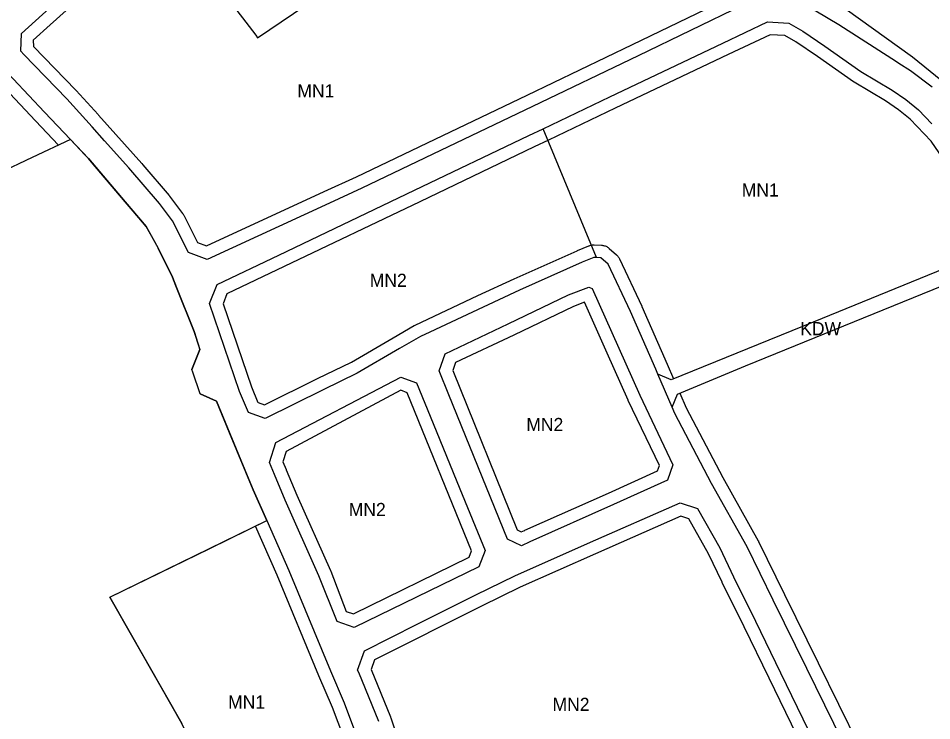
# Model space of a CAD drawing. Extents: x 7435758 to 7439981, y 5550649 to 5554049.
# Drawn here: x 7436744.6 to 7437107.4, y 5551729.4 to 5552008.2 of the extents above; entities that cross this region are included whole.
import ezdxf

# ---------------------------------------------------------------- set-up
doc = ezdxf.new("R2010")
doc.units = 0
for name, color, linetype in [('info', 7, 'Continuous'), ('linie_rozgraniczające', 7, 'Continuous'), ('linie_zabudowy_nieprzekraczalne', 7, 'Continuous'), ('oznaczenia_przeznaczen', 7, 'Continuous')]:
    doc.layers.add(name, color=color, linetype=linetype)

msp = doc.modelspace()

# ---------------------------------------------------------------- linework, layer by layer
at = {"layer": 'info'}
for p, q in [((7436765.31, 5551960.09), (7436750.08, 5551952.93)), ((7436770.99, 5551954.08), (7436765.31, 5551960.09)), ((7436750.08, 5551952.93), (7436736.66, 5551946.62)), ((7436772.47, 5551952.51), (7436770.99, 5551954.08)), ((7436773.71, 5551951.06), (7436772.47, 5551952.51)), ((7436787.1, 5551935.35), (7436773.71, 5551951.06)), ((7436790.22, 5551931.69), (7436787.1, 5551935.35)), ((7436800.14, 5551917.03), (7436799.3, 5551918.56)), ((7436805.8, 5551905.51), (7436800.14, 5551917.03)), ((7436806.26, 5551904.37), (7436805.8, 5551905.51)), ((7436807.49, 5551901.3), (7436806.26, 5551904.37)), ((7436816.38, 5551877.81), (7436814.47, 5551883.86)), ((7436813.57, 5551868.84), (7436816.73, 5551876.72)), ((7436816.73, 5551876.72), (7436816.38, 5551877.81)), ((7436816.82, 5551859.18), (7436813.95, 5551867.7)), ((7436823.3, 5551856.25), (7436819.17, 5551858.12)), ((7436828.51, 5551843.7), (7436823.3, 5551856.25)), ((7436820.63, 5551797.79), (7436843.32, 5551808.82)), ((7436780.9, 5551778.49), (7436820.63, 5551797.79)), ((7436800.79, 5551743.61), (7436780.9, 5551778.49))]:
    msp.add_line(p, q, dxfattribs=at)
for points in [[(7436799.3, 5551918.56), (7436795.43, 5551925.58), (7436790.22, 5551931.69)], [(7436814.47, 5551883.86), (7436807.49, 5551901.3), (7436807.49, 5551901.3)], [(7436813.95, 5551867.7), (7436813.57, 5551868.84), (7436813.57, 5551868.84)], [(7436819.17, 5551858.12), (7436816.82, 5551859.18), (7436816.82, 5551859.18)], [(7436843.32, 5551808.82), (7436837.92, 5551821.02), (7436828.51, 5551843.7)], [(7436830.9, 5551685.83), (7436821.23, 5551704.3), (7436809.54, 5551728.26), (7436800.79, 5551743.61)]]:
    msp.add_lwpolyline(points, dxfattribs=at)
at = {"layer": 'linie_rozgraniczające'}
for p, q in [((7436839.63, 5552000.51), (7436921.59, 5552055.85)), ((7437070.47, 5552005.57), (7437031.54, 5552029.05)), ((7436821.74, 5552024.08), (7436838.9, 5552001.48)), ((7436745.81, 5552002.16), (7436756.98, 5552012.28)), ((7437032.35, 5552013.43), (7436990.74, 5551993.3)), ((7437024.47, 5551998.39), (7437042.18, 5552006.77)), ((7437042.18, 5552006.77), (7437050.58, 5552006.33)), ((7437050.58, 5552006.33), (7437056.14, 5552003.08)), ((7437093.35, 5551990.97), (7437070.47, 5552005.57)), ((7436745.58, 5551995.13), (7436745.81, 5552002.16)), ((7436838.9, 5552001.48), (7436839.63, 5552000.51)), ((7437056.14, 5552003.08), (7437064.9, 5551997.13)), ((7436728.65, 5551998.96), (7436755.06, 5551970.94)), ((7436979.51, 5551977.03), (7437024.47, 5551998.39)), ((7436746.75, 5551993.82), (7436745.58, 5551995.13)), ((7437064.9, 5551997.13), (7437079.2, 5551987.14)), ((7436763.86, 5551976.21), (7436746.75, 5551993.82)), ((7436990.74, 5551993.3), (7436948.86, 5551973.25)), ((7437094.34, 5551990.32), (7437093.35, 5551990.97)), ((7437079.2, 5551987.14), (7437091.67, 5551979.69)), ((7437098.92, 5551987.32), (7437094.34, 5551990.32)), ((7437107.51, 5551980.83), (7437098.92, 5551987.32)), ((7437091.67, 5551979.69), (7437097.16, 5551975.95)), ((7436773.94, 5551965.1), (7436763.86, 5551976.21)), ((7436953.08, 5551964.39), (7436979.51, 5551977.03)), ((7437097.16, 5551975.95), (7437102.2, 5551971.89)), ((7436948.86, 5551973.25), (7436912.27, 5551955.75)), ((7436755.06, 5551970.94), (7436765.31, 5551960.09)), ((7437102.2, 5551971.89), (7437107.45, 5551966.38)), ((7436778.9, 5551959.57), (7436773.94, 5551965.1)), ((7436901.97, 5551939.94), (7436947.39, 5551961.66)), ((7436947.39, 5551961.66), (7436953.08, 5551964.39)), ((7436974.19, 5551913.22), (7436953.08, 5551964.39)), ((7436765.31, 5551960.09), (7436750.08, 5551952.93)), ((7436765.31, 5551960.09), (7436772.47, 5551952.52)), ((7436788.47, 5551948.91), (7436778.9, 5551959.57)), ((7436912.27, 5551955.75), (7436881.03, 5551940.82)), ((7436750.08, 5551952.93), (7436736.66, 5551946.62)), ((7436772.47, 5551952.52), (7436787.1, 5551935.35)), ((7436800.66, 5551934.67), (7436788.47, 5551948.91)), ((7436848.07, 5551914.24), (7436901.97, 5551939.94)), ((7436881.03, 5551940.82), (7436868.15, 5551934.9)), ((7436787.1, 5551935.35), (7436795.43, 5551925.58)), ((7436805.86, 5551927.78), (7436800.66, 5551934.67)), ((7436868.15, 5551934.9), (7436819.57, 5551912.53)), ((7436795.43, 5551925.58), (7436800.14, 5551917.03)), ((7436812.2, 5551915.2), (7436805.86, 5551927.78)), ((7436800.14, 5551917.03), (7436805.8, 5551905.51)), ((7436819.57, 5551912.53), (7436812.2, 5551915.2)), ((7436823.55, 5551902.55), (7436848.07, 5551914.24)), ((7437131.52, 5551916.61), (7437060.3, 5551887.61)), ((7436968.62, 5551911.41), (7436943.64, 5551900.28)), ((7436973.13, 5551913.27), (7436968.62, 5551911.41)), ((7436974.19, 5551913.22), (7436973.13, 5551913.27)), ((7436976, 5551913.14), (7436974.19, 5551913.22)), ((7436978.85, 5551910.62), (7436976, 5551913.14)), ((7436987.7, 5551891.81), (7436978.85, 5551910.62)), ((7437033.37, 5551870.27), (7437132.96, 5551910.8)), ((7436805.8, 5551905.51), (7436807.49, 5551901.3)), ((7436807.49, 5551901.3), (7436814.47, 5551883.86)), ((7436820.59, 5551895.04), (7436823.55, 5551902.55)), ((7436943.64, 5551900.28), (7436929.24, 5551893.62)), ((7436963.17, 5551898.46), (7436971.25, 5551901.55)), ((7436971.25, 5551901.55), (7436972.59, 5551900.95)), ((7436972.59, 5551900.95), (7436983.12, 5551877.27)), ((7436939.19, 5551886.99), (7436963.17, 5551898.46)), ((7436832.51, 5551860.14), (7436820.59, 5551895.04)), ((7436929.24, 5551893.62), (7436908.07, 5551883.69)), ((7436997.78, 5551868.89), (7436987.7, 5551891.81)), ((7436914.1, 5551874.97), (7436939.19, 5551886.99)), ((7437060.3, 5551887.61), (7437003.93, 5551864.69)), ((7436814.47, 5551883.86), (7436816.73, 5551876.72)), ((7436904.34, 5551881.94), (7436896.06, 5551877.12)), ((7436908.07, 5551883.69), (7436904.34, 5551881.94)), ((7436816.73, 5551876.72), (7436813.57, 5551868.83)), ((7436896.06, 5551877.12), (7436879.23, 5551867.3)), ((7436911.8, 5551868.33), (7436914.1, 5551874.97)), ((7436983.12, 5551877.27), (7436991.4, 5551858.61)), ((7436879.23, 5551867.3), (7436865.64, 5551860.75)), ((7436915.66, 5551858.81), (7436911.8, 5551868.33)), ((7436998.63, 5551866.9), (7436997.78, 5551868.89)), ((7437006.37, 5551859.03), (7437033.37, 5551870.27)), ((7436846.88, 5551839.8), (7436896.55, 5551865.82)), ((7436896.55, 5551865.82), (7436902.82, 5551863.53)), ((7436902.82, 5551863.53), (7436909.39, 5551847.42)), ((7437004.26, 5551853.86), (7436998.63, 5551866.9)), ((7437003.93, 5551864.69), (7436998.63, 5551866.9)), ((7436836, 5551851.72), (7436832.51, 5551860.14)), ((7436865.64, 5551860.75), (7436842.71, 5551849.4)), ((7436816.82, 5551859.18), (7436823.3, 5551856.25)), ((7436823.3, 5551856.25), (7436835.56, 5551826.72)), ((7436938.88, 5551801.5), (7436915.66, 5551858.81)), ((7436991.4, 5551858.61), (7437004.63, 5551831.03)), ((7437004.26, 5551853.86), (7437006.37, 5551859.03)), ((7437005.34, 5551851.36), (7437004.26, 5551853.86)), ((7436842.71, 5551849.4), (7436836, 5551851.72)), ((7437019.99, 5551823.59), (7437005.34, 5551851.36)), ((7436909.39, 5551847.42), (7436919.95, 5551821.49)), ((7436844.36, 5551831.88), (7436846.88, 5551839.8)), ((7436846.42, 5551827.1), (7436844.36, 5551831.88)), ((7437004.63, 5551831.03), (7437002.49, 5551824.88)), ((7436835.56, 5551826.72), (7436837.92, 5551821.02)), ((7436850.66, 5551816.89), (7436846.42, 5551827.1)), ((7437002.49, 5551824.88), (7436981.04, 5551815.18)), ((7437034.14, 5551798.36), (7437019.99, 5551823.59)), ((7436837.92, 5551821.02), (7436843.32, 5551808.82)), ((7436919.95, 5551821.49), (7436929.97, 5551796.91)), ((7436864.03, 5551786.96), (7436850.66, 5551816.89)), ((7436981.04, 5551815.18), (7436947.83, 5551800.44)), ((7436971.87, 5551800.23), (7437007.45, 5551815.89)), ((7437007.45, 5551815.89), (7437014.33, 5551813.62)), ((7437014.33, 5551813.62), (7437023.17, 5551797.98)), ((7436780.9, 5551778.49), (7436843.32, 5551808.82)), ((7436843.32, 5551808.82), (7436852.06, 5551789.07)), ((7436944.43, 5551798.78), (7436938.88, 5551801.5)), ((7436941.79, 5551786.92), (7436971.87, 5551800.23)), ((7436947.83, 5551800.44), (7436944.43, 5551798.78)), ((7437044.46, 5551777.27), (7437034.14, 5551798.36)), ((7436929.97, 5551796.91), (7436927.54, 5551790.54)), ((7437023.17, 5551797.98), (7437028.72, 5551786.51)), ((7436852.06, 5551789.07), (7436868.57, 5551749.17)), ((7436927.54, 5551790.54), (7436878.05, 5551766.39)), ((7436871.28, 5551768.74), (7436864.03, 5551786.96)), ((7436926.35, 5551779.35), (7436941.79, 5551786.92)), ((7437028.72, 5551786.51), (7437037.34, 5551768.88)), ((7436780.9, 5551778.49), (7436809.54, 5551728.26)), ((7436903.06, 5551767.66), (7436926.35, 5551779.35)), ((7437057.78, 5551750.11), (7437044.46, 5551777.27)), ((7436878.05, 5551766.39), (7436871.28, 5551768.74)), ((7436882.05, 5551757.11), (7436903.06, 5551767.66)), ((7437037.34, 5551768.88), (7437047.32, 5551748.47)), ((7436879.38, 5551749.51), (7436882.05, 5551757.11)), ((7436868.57, 5551749.17), (7436874, 5551736.55)), ((7436879.8, 5551748.53), (7436879.38, 5551749.51)), ((7436887.83, 5551729.05), (7436879.8, 5551748.53)), ((7437047.32, 5551748.47), (7437060.55, 5551721.15)), ((7437073.91, 5551717.41), (7437057.78, 5551750.11)), ((7436874, 5551736.55), (7436878.59, 5551724.44))]:
    msp.add_line(p, q, dxfattribs=at)
at = {"layer": 'linie_zabudowy_nieprzekraczalne'}
for points in [[(7436934.74, 5552091.63), (7436998.26, 5552057.84), (7437062.75, 5552019.65), (7437099.78, 5551992.9), (7437113.79, 5551981.52)], [(7436771.3, 5552018.3), (7436757.24, 5552005.64), (7436750.48, 5551999.55), (7436750.64, 5551996.99), (7436767.45, 5551979.69), (7436767.48, 5551979.66), (7436767.56, 5551979.57), (7436776.31, 5551970), (7436776.51, 5551969.78), (7436793.62, 5551950.58), (7436794.11, 5551950.01), (7436804.46, 5551937.92), (7436804.5, 5551937.87), (7436804.65, 5551937.68), (7436809.85, 5551930.79), (7436809.9, 5551930.72), (7436810.08, 5551930.45), (7436810.25, 5551930.17), (7436810.32, 5551930.03), (7436815.77, 5551919.23), (7436819.34, 5551917.93), (7436866.06, 5551939.44), (7436878.9, 5551945.35), (7436878.91, 5551945.35), (7436910.11, 5551960.26), (7436946.7, 5551977.76), (7436988.58, 5551997.81), (7437025.03, 5552015.44)], [(7437113.57, 5551950.23), (7437107.2, 5551959.4), (7437098.81, 5551968.2), (7437094.18, 5551971.93), (7437088.98, 5551975.47), (7437076.64, 5551982.85), (7437076.6, 5551982.87), (7437076.34, 5551983.04), (7437062.06, 5551993.01), (7437053.47, 5551998.85), (7437049.11, 5552001.4), (7437043.18, 5552001.71), (7437026.61, 5551993.87), (7436981.66, 5551972.52), (7436955.24, 5551959.88), (7436949.54, 5551957.15), (7436904.13, 5551935.43), (7436904.12, 5551935.43), (7436904.12, 5551935.43), (7436850.22, 5551909.73), (7436827.48, 5551898.88), (7436825.92, 5551894.92), (7436837.19, 5551861.91), (7436839.78, 5551855.65)], [(7436760.55, 5551957.85), (7436751.43, 5551967.5), (7436751.42, 5551967.51), (7436725.01, 5551995.53)], [(7436793.62, 5551950.58), (7436793.61, 5551950.44)], [(7436839.85, 5551855.68), (7436842.36, 5551854.81), (7436863.42, 5551865.24), (7436863.47, 5551865.26), (7436876.88, 5551871.72), (7436893.55, 5551881.44), (7436901.82, 5551886.26), (7436901.94, 5551886.33), (7436902.21, 5551886.46), (7436927.12, 5551898.14), (7436927.14, 5551898.15), (7436941.54, 5551904.82), (7436941.61, 5551904.85), (7436966.58, 5551915.98), (7436966.71, 5551916.03), (7436971.22, 5551917.89), (7436971.33, 5551917.94), (7436971.64, 5551918.04), (7436971.95, 5551918.13), (7436972.27, 5551918.2), (7436972.6, 5551918.24), (7436972.92, 5551918.27), (7436973.25, 5551918.27), (7436973.35, 5551918.26), (7436976.22, 5551918.14), (7436976.45, 5551918.12), (7436976.77, 5551918.08), (7436977.09, 5551918.02), (7436977.41, 5551917.94), (7436977.72, 5551917.84), (7436978.03, 5551917.71), (7436978.32, 5551917.57), (7436978.6, 5551917.41), (7436978.88, 5551917.23), (7436979.14, 5551917.03), (7436979.31, 5551916.89), (7436982.16, 5551914.36), (7436982.24, 5551914.29), (7436982.47, 5551914.06), (7436982.69, 5551913.82), (7436982.89, 5551913.56), (7436983.08, 5551913.29), (7436983.24, 5551913.01), (7436983.37, 5551912.74), (7436992.22, 5551893.94), (7436992.24, 5551893.91), (7436992.28, 5551893.82), (7437002.36, 5551870.9), (7437002.37, 5551870.87), (7437004.87, 5551865.07)], [(7436944.28, 5551804.42), (7436945.64, 5551804.93), (7436945.73, 5551804.97), (7436945.8, 5551805.01), (7436979, 5551819.74), (7436998.47, 5551828.55), (7436999.23, 5551830.72), (7436986.89, 5551856.45), (7436986.87, 5551856.51), (7436986.83, 5551856.58), (7436978.55, 5551875.24), (7436969.52, 5551895.54), (7436965.14, 5551893.87), (7436941.35, 5551882.48), (7436918.21, 5551871.56), (7436917.14, 5551868.47), (7436942.79, 5551805.15), (7436944.28, 5551804.42)], [(7436849.68, 5551832.18), (7436851.01, 5551829.07), (7436851.03, 5551829.02), (7436855.25, 5551818.87), (7436868.59, 5551789), (7436868.67, 5551788.81), (7436874.8, 5551772.81), (7436877.73, 5551771.8), (7436923.62, 5551794.27), (7436924.6, 5551796.85), (7436899.03, 5551859.59), (7436896.51, 5551860.55), (7436851.02, 5551836.32), (7436849.71, 5551832.19)], [(7437007.31, 5551859.42), (7437009.85, 5551853.53), (7437024.38, 5551825.98), (7437038.5, 5551800.8), (7437038.53, 5551800.75), (7437038.63, 5551800.55), (7437048.95, 5551779.47), (7437062.27, 5551752.32), (7437078.39, 5551719.62), (7437078.45, 5551719.51), (7437078.47, 5551719.46), (7437084.33, 5551706.44), (7437098.81, 5551674.26), (7437098.81, 5551674.26), (7437102.22, 5551666.67), (7437104.72, 5551662.82)], [(7437056.03, 5551719), (7437042.82, 5551746.29), (7437032.85, 5551766.68), (7437024.22, 5551784.31), (7437024.21, 5551784.34), (7437018.74, 5551795.66), (7437010.93, 5551809.48), (7437007.71, 5551810.54), (7436973.88, 5551795.66), (7436943.9, 5551782.39), (7436928.57, 5551774.87), (7436886.09, 5551753.55), (7436884.76, 5551749.74)], [(7436873.86, 5551722.79), (7436869.36, 5551734.67), (7436863.97, 5551747.19), (7436863.95, 5551747.26), (7436847.46, 5551787.11), (7436838.82, 5551806.63)], [(7436884.7, 5551749.76), (7436892.45, 5551730.95), (7436892.49, 5551730.85), (7436892.58, 5551730.61), (7436897.85, 5551714.51)]]:
    msp.add_lwpolyline(points, dxfattribs=at)

# ---------------------------------------------------------------- texts
at = {"layer": 'oznaczenia_przeznaczen'}
for s, p in [('MN1', (7436855.45, 5551976.81)), ('MN1', (7437031.96, 5551937.46)), ('MN2', (7436884.2, 5551901.61)), ('KDW', (7437055.17, 5551882.44)), ('MN2', (7436946.38, 5551844.39)), ('MN2', (7436875.85, 5551810.65)), ('MN1', (7436827.92, 5551734.21)), ('MN2', (7436956.8, 5551733.29))]:
    msp.add_text(s, height=5.2, dxfattribs=at).set_placement(p)

doc.saveas('drawing.dxf')
